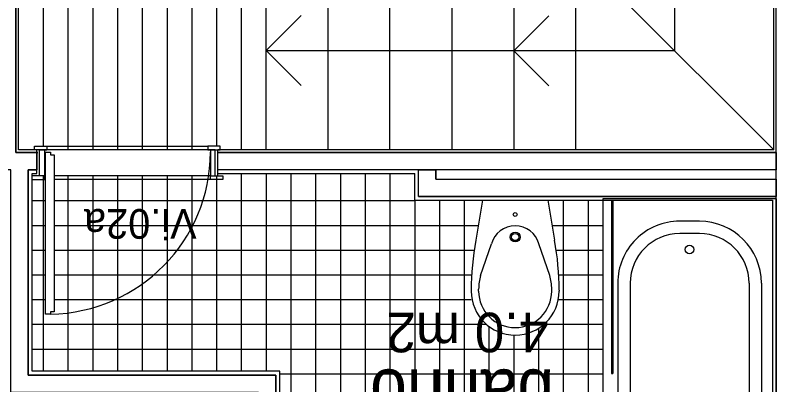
# Model space of a CAD drawing. Extents: x 1278 to 1356, y -253.7 to -224.
# Drawn here: x 1331.53 to 1334.624, y -239.375 to -237.882 of the extents above; entities that cross this region are included whole.
import ezdxf

# ---------------------------------------------------------------- set-up
doc = ezdxf.new("R2010")
doc.units = 0
for name, color, linetype in [('Level 1', 7, 'Continuous'), ('Level 10', 7, 'Continuous'), ('Level 11', 7, 'Continuous'), ('Level 13', 7, 'Continuous'), ('Level 2', 7, 'Continuous'), ('Level 36', 7, 'Continuous'), ('Level 4', 7, 'Continuous'), ('Level 40', 7, 'Continuous'), ('Level 60', 7, 'Continuous'), ('Level 65', 7, 'Continuous'), ('Level 66', 7, 'Continuous'), ('Level 67', 7, 'Continuous')]:
    doc.layers.add(name, color=color, linetype=linetype)

msp = doc.modelspace()

# ---------------------------------------------------------------- linework, layer by layer
at = {"layer": 'Level 1'}
for p, q in [((1331.5325, -238.4357), (1331.5325, -236.6557)), ((1331.6175, -238.4357), (1331.5325, -238.4357)), ((1331.6175, -238.5207), (1331.6175, -238.4257)), ((1332.3475, -238.5307), (1332.3475, -238.4257)), ((1334.6025, -238.4357), (1332.3475, -238.4357)), ((1331.5825, -239.3357), (1331.5825, -238.5057)), ((1331.5825, -238.5057), (1331.6175, -238.5057)), ((1333.1575, -238.5057), (1332.3475, -238.5057)), ((1334.6025, -238.5057), (1333.2275, -238.5057)), ((1334.6025, -240.234), (1334.6025, -238.614)), ((1332.5825, -239.3357), (1331.5825, -239.3357)), ((1332.5825, -240.234), (1332.5825, -239.3357))]:
    msp.add_line(p, q, dxfattribs=at)
at = {"layer": 'Level 10'}
for p, q in [((1331.6425, -235.7207), (1331.6425, -238.4107)), ((1331.7425, -235.7207), (1331.7425, -238.4257)), ((1331.8425, -235.7207), (1331.8425, -238.4257)), ((1331.9425, -235.7207), (1331.9425, -238.4257)), ((1332.0425, -235.7207), (1332.0425, -238.4257)), ((1332.1425, -235.7207), (1332.1425, -238.4257)), ((1332.2425, -235.7207), (1332.2425, -238.4257)), ((1332.3425, -235.7207), (1332.3425, -238.4107)), ((1332.4425, -236.6557), (1332.4425, -238.4257)), ((1332.3075, -238.4257), (1331.6575, -238.4257)), ((1332.4425, -238.5207), (1332.4425, -239.3207)), ((1332.5425, -238.5207), (1332.5425, -239.3207)), ((1332.6425, -238.5207), (1332.6425, -239.669)), ((1332.7425, -238.5207), (1332.7425, -239.669)), ((1332.8425, -238.5207), (1332.8425, -239.669)), ((1332.9425, -238.5207), (1332.9425, -239.669)), ((1333.0425, -238.5207), (1333.0425, -239.669)), ((1331.6425, -238.5307), (1331.6425, -239.3207)), ((1332.3175, -238.5307), (1331.6875, -238.5307)), ((1331.7425, -238.5307), (1331.7425, -239.3207)), ((1331.8425, -238.5307), (1331.8425, -239.3207)), ((1331.9425, -238.5307), (1331.9425, -239.3207)), ((1332.0425, -238.5307), (1332.0425, -239.3207)), ((1332.1425, -238.5307), (1332.1425, -239.3207)), ((1332.2425, -238.5307), (1332.2425, -239.3207)), ((1332.3425, -238.5307), (1332.3425, -239.3207)), ((1331.5975, -238.6307), (1331.6525, -238.6307)), ((1331.6875, -238.6307), (1333.1425, -238.6307)), ((1333.1425, -238.629), (1333.1425, -239.669)), ((1333.2425, -238.629), (1333.2425, -240.219)), ((1333.3425, -238.629), (1333.3425, -240.219)), ((1333.7425, -238.629), (1333.7425, -240.219)), ((1333.8425, -238.629), (1333.8425, -240.219)), ((1331.5975, -238.7307), (1331.6525, -238.7307)), ((1331.6875, -238.7307), (1333.3991, -238.7307)), ((1333.6972, -238.7307), (1333.9025, -238.7307)), ((1331.5975, -238.8307), (1331.6525, -238.8307)), ((1331.6875, -238.8307), (1333.3827, -238.8307)), ((1333.7137, -238.8307), (1333.9025, -238.8307)), ((1331.5975, -238.9307), (1331.6525, -238.9307)), ((1331.6875, -238.9307), (1333.3724, -238.9307)), ((1333.7239, -238.9307), (1333.9025, -238.9307)), ((1331.5975, -239.0307), (1331.6525, -239.0307)), ((1331.6875, -239.0307), (1333.3707, -239.0307)), ((1333.7223, -239.0307), (1333.9025, -239.0307)), ((1331.5975, -239.1307), (1333.4321, -239.1307)), ((1333.4425, -239.1391), (1333.4425, -239.7067)), ((1333.6425, -239.1468), (1333.6425, -239.7067)), ((1333.6643, -239.1307), (1333.9025, -239.1307)), ((1333.5425, -239.1739), (1333.5425, -239.6759)), ((1331.5975, -239.2307), (1333.9025, -239.2307)), ((1332.5975, -239.3307), (1333.9025, -239.3307))]:
    msp.add_line(p, q, dxfattribs=at)
at = {"layer": 'Level 11'}
for p, q in [((1333.4158, -238.629), (1333.3892, -238.791)), ((1333.4158, -238.629), (1333.6805, -238.629)), ((1333.6805, -238.629), (1333.7071, -238.791)), ((1334.6025, -238.624), (1333.9025, -238.624)), ((1333.9025, -238.624), (1333.9025, -240.224)), ((1334.6025, -238.624), (1334.6025, -240.224)), ((1334.2925, -238.714), (1334.2125, -238.714)), ((1334.2925, -238.764), (1334.2125, -238.764)), ((1333.4083, -238.9335), (1333.452, -238.8055)), ((1333.688, -238.9335), (1333.6443, -238.8055)), ((1333.3707, -238.9931), (1333.3707, -238.9968)), ((1333.4007, -238.9965), (1333.4007, -238.9884)), ((1333.6957, -238.9965), (1333.6957, -238.9884)), ((1333.7257, -238.9931), (1333.7257, -238.9968)), ((1333.9625, -238.964), (1333.9625, -240.014)), ((1334.0125, -238.964), (1334.0125, -239.914)), ((1334.4925, -238.964), (1334.4925, -239.914)), ((1334.5425, -238.964), (1334.5425, -240.014))]:
    msp.add_line(p, q, dxfattribs=at)
for centre, radius in [((1333.5482, -238.687), 0.00766), ((1333.5482, -238.7778), 0.02), ((1333.5482, -238.7778), 0.0146), ((1334.2525, -238.8284), 0.0173)]:
    msp.add_circle(centre, radius, dxfattribs=at)
for centre, radius, start, end in [((1334.2125, -238.964), 0.25, 89.9999, 180), ((1334.2925, -238.964), 0.25, 0.0001, 90.0001), ((1333.5482, -238.833), 0.1, 15.9317, 164.1953), ((1334.2125, -238.964), 0.2, 90, 180), ((1334.2925, -238.964), 0.2, 360, 90), ((1333.6007, -238.9884), 0.2, 164.0693, 180.0006), ((1333.4957, -238.9884), 0.2, 0.0017, 15.9319), ((1333.5482, -238.9965), 0.1775, 180.0002, 359.9999), ((1333.5482, -238.9965), 0.1475, 180.0002, 359.9999)]:
    msp.add_arc(centre, radius, start, end, dxfattribs=at)
for centre, major_axis, start_param, end_param in [((1334.7707, -238.9931), (-1.4, 0), 6.120269, 6.283187), ((1332.3257, -238.9931), (1.4, 0), 6.283183, 6.446102)]:
    msp.add_ellipse(centre, major_axis=major_axis, ratio=0.88995, start_param=start_param, end_param=end_param, dxfattribs=at)
at = {"layer": 'Level 13'}
for p, q in [((1331.6075, -238.4107), (1331.6575, -238.4107)), ((1331.6075, -238.4257), (1331.6075, -238.4107)), ((1331.6575, -238.4257), (1331.6075, -238.4257)), ((1331.6275, -238.5307), (1331.6275, -238.4257)), ((1331.6275, -238.4257), (1331.6575, -238.4257)), ((1331.6475, -238.4257), (1331.6475, -238.5307)), ((1331.6525, -239.0901), (1331.6525, -238.4351)), ((1331.6525, -238.4351), (1331.6725, -238.4351)), ((1331.6575, -238.4107), (1331.6575, -238.4257)), ((1331.6725, -238.4351), (1331.6725, -238.4451)), ((1332.3575, -238.4107), (1332.3075, -238.4107)), ((1332.3075, -238.4107), (1332.3075, -238.4257)), ((1332.3375, -238.4257), (1332.3075, -238.4257)), ((1332.3075, -238.4257), (1332.3575, -238.4257)), ((1332.3175, -238.4257), (1332.3175, -238.5307)), ((1332.3375, -238.5307), (1332.3375, -238.4257)), ((1332.3575, -238.4257), (1332.3575, -238.4107)), ((1331.6725, -238.4451), (1331.6875, -238.4451)), ((1331.6875, -238.4451), (1331.6875, -239.0801)), ((1331.6475, -238.5307), (1331.5975, -238.5307)), ((1331.5975, -238.5457), (1331.6475, -238.5457)), ((1331.6475, -238.5307), (1331.6275, -238.5307)), ((1331.6475, -238.5457), (1331.6475, -238.5307)), ((1332.3175, -238.5457), (1332.3175, -238.5307)), ((1332.3175, -238.5307), (1332.3375, -238.5307)), ((1332.3175, -238.5307), (1332.3675, -238.5307)), ((1332.3675, -238.5457), (1332.3175, -238.5457)), ((1332.3675, -238.5307), (1332.3675, -238.5457)), ((1331.6725, -239.0801), (1331.6725, -239.0898)), ((1331.6875, -239.0801), (1331.6725, -239.0801)), ((1331.6725, -239.0901), (1331.6525, -239.0901))]:
    msp.add_line(p, q, dxfattribs=at)
at = {"layer": 'Level 2'}
for p, q in [((1334.1925, -238.0257), (1334.1925, -237.2257)), ((1333.7925, -237.6257), (1334.5925, -238.4257)), ((1332.5425, -238.424), (1332.5425, -237.6557)), ((1332.7925, -238.424), (1332.7925, -237.654)), ((1333.0425, -238.424), (1333.0425, -237.654)), ((1333.2925, -237.654), (1333.2925, -238.424)), ((1333.5425, -237.654), (1333.5425, -238.424)), ((1333.7925, -238.4257), (1333.7925, -237.6557)), ((1332.6839, -237.8826), (1332.5425, -238.024)), ((1333.6839, -237.8843), (1333.5425, -238.0257)), ((1332.6839, -238.1654), (1332.5425, -238.024)), ((1334.1925, -238.0257), (1332.5425, -238.0257)), ((1333.6839, -238.1672), (1333.5425, -238.0257))]:
    msp.add_line(p, q, dxfattribs=at)
at = {"layer": 'Level 36'}
for p, q in [((1333.9369, -238.629), (1333.9369, -239.329)), ((1333.9419, -238.629), (1333.9419, -239.329)), ((1333.9369, -239.329), (1333.9419, -239.329))]:
    msp.add_line(p, q, dxfattribs=at)
at = {"layer": 'Level 4'}
for p, q in [((1331.6575, -238.4107), (1332.3075, -238.4107)), ((1332.3175, -238.5457), (1331.6875, -238.5457))]:
    msp.add_line(p, q, dxfattribs=at)
msp.add_ellipse((1331.6589, -238.435), major_axis=(-0.6586, 0), ratio=0.994279, start_param=1.591512, end_param=3.141593, dxfattribs=at)
at = {"layer": 'Level 65'}
for p, q in [((1331.5425, -238.4257), (1331.5425, -236.6557)), ((1334.5925, -238.4257), (1334.5925, -236.8257)), ((1334.5925, -238.4257), (1334.5925, -236.8257)), ((1331.6175, -238.4257), (1331.5425, -238.4257)), ((1334.5925, -238.4257), (1332.3475, -238.4257)), ((1331.5975, -239.3207), (1331.5975, -238.5207)), ((1331.5975, -238.5207), (1331.6175, -238.5207)), ((1332.3475, -238.5207), (1333.1425, -238.5207)), ((1333.1425, -238.629), (1333.1425, -238.5207)), ((1333.1425, -238.629), (1334.5875, -238.629)), ((1334.5875, -238.629), (1334.5875, -240.219)), ((1332.5975, -239.3207), (1331.5975, -239.3207)), ((1332.5975, -240.219), (1332.5975, -239.3207))]:
    msp.add_line(p, q, dxfattribs=at)
at = {"layer": 'Level 66'}
for p, q in [((1334.6025, -238.4357), (1334.6025, -236.8157)), ((1333.1575, -238.614), (1333.1575, -238.5057)), ((1333.2275, -238.544), (1333.2275, -238.5057)), ((1334.6025, -238.544), (1334.6025, -238.5057)), ((1333.2275, -238.544), (1334.6025, -238.544)), ((1333.1575, -238.614), (1334.6025, -238.614))]:
    msp.add_line(p, q, dxfattribs=at)
at = {"layer": 'Level 67'}
for points in [[(1334.6025, -240.234), (1334.6025, -240.304), (1332.5125, -240.304), (1332.5125, -239.4057), (1331.5125, -239.4057), (1331.5125, -238.5057), (1330.3525, -238.5057), (1330.3525, -238.244), (1329.4325, -238.244), (1329.4325, -238.174), (1330.4233, -238.174), (1330.4233, -238.4357), (1331.4525, -238.4357), (1331.4525, -236.6557), (1331.5325, -236.6557), (1331.5325, -238.4357), (1331.6212, -238.4357), (1331.6175, -238.4357), (1331.6175, -238.5057), (1331.5825, -238.5057), (1331.5825, -239.3357), (1332.5825, -239.3357), (1332.5825, -240.234), (1334.6025, -240.234)], [(1334.6725, -242.1713), (1334.6025, -242.1713), (1334.6025, -242.104), (1332.5275, -242.104), (1332.5275, -242.194), (1332.4575, -242.194), (1332.4575, -242.034), (1334.6025, -242.034), (1334.6025, -236.7713), (1334.6725, -236.7713)], [(1334.6025, -238.4357), (1334.6025, -238.5057), (1332.3475, -238.5057), (1332.3475, -238.4357)], [(1333.2275, -238.5057), (1333.2275, -238.544), (1334.6025, -238.544), (1334.6025, -238.614), (1333.1575, -238.614), (1333.1575, -238.5057)]]:
    msp.add_lwpolyline(points, close=True, dxfattribs=at)

# ---------------------------------------------------------------- texts
at = {"layer": 'Level 40'}
msp.add_text('Vi.02a', height=0.12, rotation=180, dxfattribs=at).set_placement((1332.2622, -238.6648))
at = {"layer": 'Level 60'}
for s, height, p in [('4.0 m2', 0.16, (1333.6826, -239.0837)), ('banho', 0.2, (1333.7059, -239.3132))]:
    msp.add_text(s, height=height, rotation=180, dxfattribs=at).set_placement(p)

doc.saveas('drawing.dxf')
